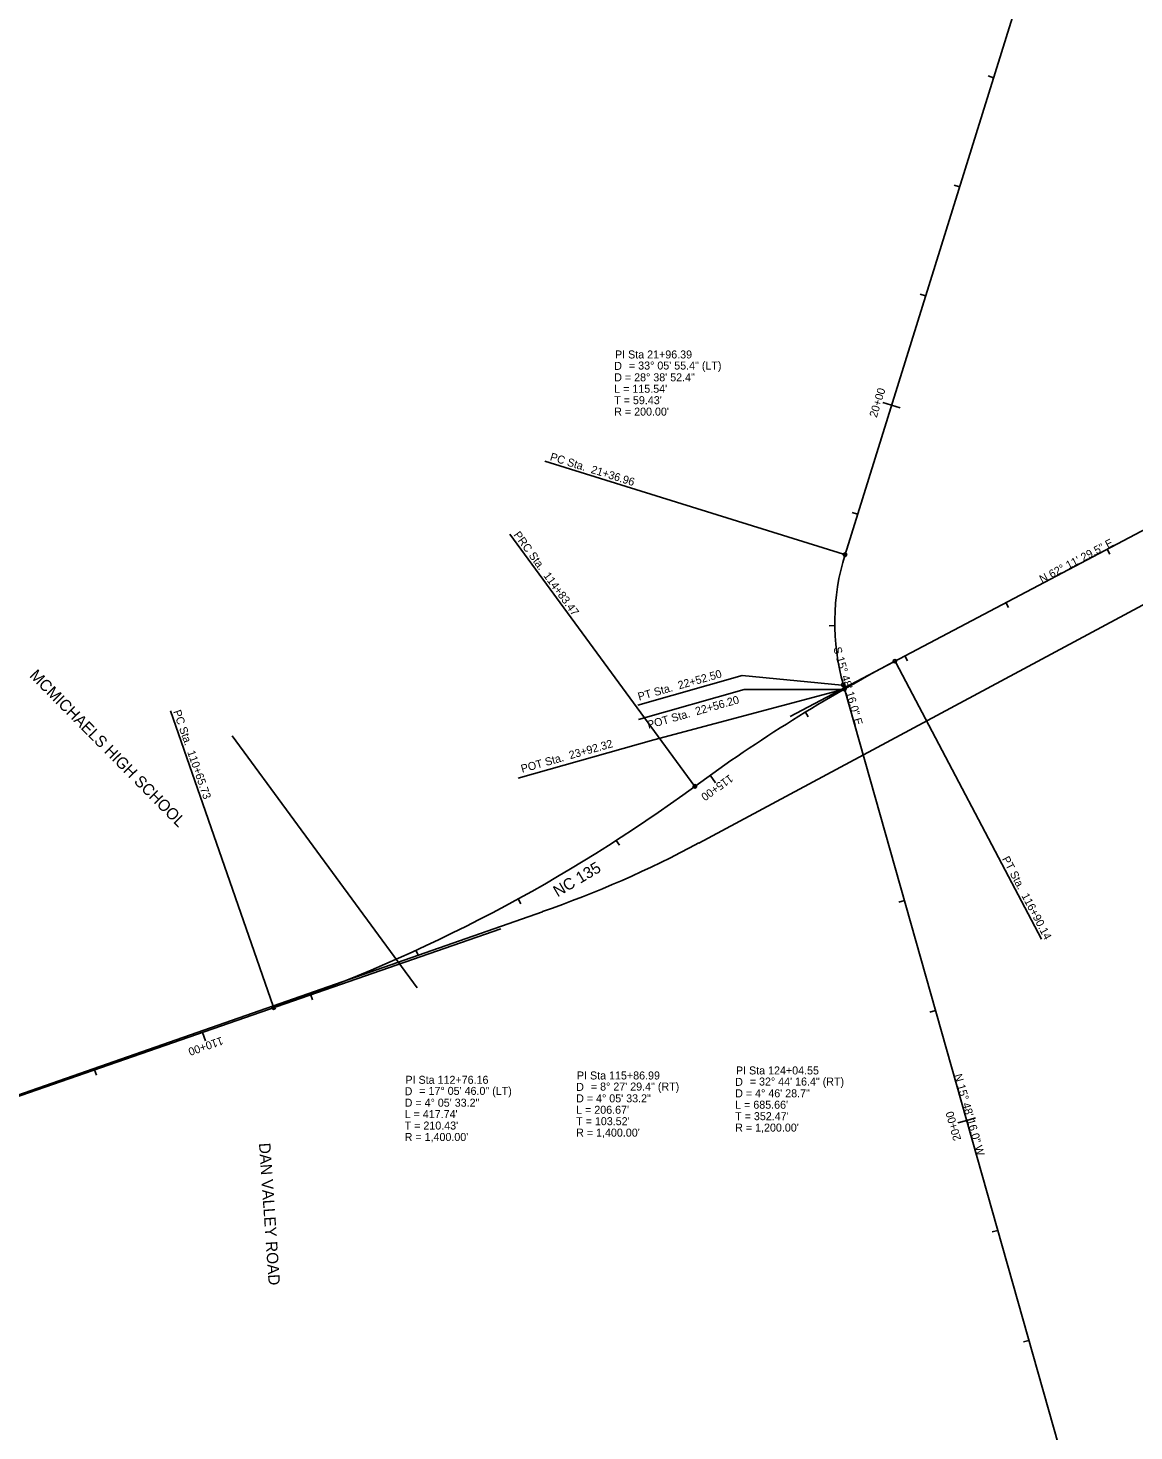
# Model space of a CAD drawing. Extents: x 1722038 to 1726172, y 967033 to 975427.
# Drawn here: x 1722928 to 1723895, y 971142 to 972370 of the extents above; entities that cross this region are included whole.
import ezdxf

# ---------------------------------------------------------------- set-up
doc = ezdxf.new("R2010")
doc.units = 0
for name, color, linetype in [('Prop Horizontal Alignment', 7, 'Continuous'), ('Prop Horizontal Alignment Curve and Spiral Data', 7, 'Continuous'), ('Prop Horizontal Alignment Direction Label', 7, 'Continuous'), ('Prop Horizontal Alignment Station Label', 7, 'Continuous'), ('Prop Horizontal Alignment Tick Label', 7, 'Continuous'), ('Prop Horizontal Alignment Tick Large', 7, 'Continuous'), ('Prop Horizontal Alignment Tick Small', 7, 'Continuous')]:
    doc.layers.add(name, color=color, linetype=linetype)

msp = doc.modelspace()

# ---------------------------------------------------------------- linework, layer by layer
at = {"layer": 'Prop Horizontal Alignment'}
for p, q in [((1723980.3, 972994.6), (1723642.3, 971909)), ((1723594.4, 971767.5), (1724317.8, 972149.1)), ((1723514.4, 971656.7), (1724119.9, 971981.6)), ((1723640.8, 971795.1), (1723641.8, 971791.5)), ((1723852.2, 971048.3), (1723641.8, 971791.5)), ((1722248.4, 971202.3), (1723377.7, 971596.6)), ((1722135.8, 971162.8), (1723341.2, 971581.8))]:
    msp.add_line(p, q, dxfattribs=at)
for centre, radius, start, end in [((1723833.3, 971849.6), 200, 162.7057, 195.8045), ((1724339.1, 970577.5), 1400, 117.8085, 126.2666), ((1722682.7, 972835.1), 1400, 289.1705, 306.2666), ((1723062.9, 972498.2), 954.9, 289.2497, 298.2178)]:
    msp.add_arc(centre, radius, start, end, dxfattribs=at)
at = {"layer": 'Prop Horizontal Alignment Station Label'}
for p, q in [((1723640.9, 971909.5), (1723379.7, 971990.8)), ((1723510.9, 971706.3), (1723349.1, 971926.8)), ((1723686.6, 971814.5), (1723814.2, 971572.6)), ((1723552.3, 971803.2), (1723461, 971777.4)), ((1723639.4, 971794.7), (1723552.3, 971803.2)), ((1723554.1, 971791), (1723461.7, 971764.8)), ((1723640.4, 971791.1), (1723475.2, 971747.1)), ((1723640.4, 971791.1), (1723554.1, 971791)), ((1723142, 971514.1), (1723052.2, 971772.5)), ((1723268.1, 971530), (1723106.3, 971750.6)), ((1723475.2, 971747.1), (1723356.5, 971713.5))]:
    msp.add_line(p, q, dxfattribs=at)
for centre in [(1723642.3, 971909), (1723685.9, 971815.8), (1723640.8, 971795.1), (1723641.8, 971791.5), (1723641.8, 971791.5), (1723510.9, 971706.3), (1723142.5, 971512.7)]:
    msp.add_circle(centre, 1.5, dxfattribs=at)
at = {"layer": 'Prop Horizontal Alignment Tick Large'}
for p, q in [((1723683, 972039.8), (1723675.4, 972042.2)), ((1723683, 972039.8), (1723690.6, 972037.4)), ((1723524.3, 971716), (1723528.9, 971709.5)), ((1723080.4, 971491.1), (1723083, 971483.6)), ((1723748.7, 971414.1), (1723741, 971411.9)), ((1723748.7, 971414.1), (1723756.4, 971416.2))]:
    msp.add_line(p, q, dxfattribs=at)
at = {"layer": 'Prop Horizontal Alignment Tick Small'}
for p, q in [((1723772.2, 972326.2), (1723767.4, 972327.7)), ((1723742.5, 972230.8), (1723737.7, 972232.3)), ((1723712.7, 972135.3), (1723708, 972136.8)), ((1723653.3, 971944.3), (1723648.5, 971945.8)), ((1723871.6, 971913.7), (1723873.9, 971909.3)), ((1723783.1, 971867.1), (1723785.4, 971862.7)), ((1723633.3, 971846.9), (1723628.3, 971846.8)), ((1723694.7, 971820.4), (1723697, 971816)), ((1723607.6, 971771.2), (1723610.2, 971767)), ((1723442.2, 971659), (1723444.9, 971654.8)), ((1723356.3, 971607.8), (1723358.7, 971603.4)), ((1723694.2, 971606.5), (1723689.4, 971605.1)), ((1723267, 971562.8), (1723269.1, 971558.3)), ((1723174.7, 971524.4), (1723176.5, 971519.7)), ((1723721.4, 971510.3), (1723716.6, 971508.9)), ((1722985.9, 971458.3), (1722987.6, 971453.6)), ((1723775.9, 971317.8), (1723771.1, 971316.5)), ((1723803.1, 971221.6), (1723798.3, 971220.3))]:
    msp.add_line(p, q, dxfattribs=at)

# ---------------------------------------------------------------- texts
at = {"layer": 'Prop Horizontal Alignment Curve and Spiral Data'}
for s, p in [('PI Sta 21+96.39', (1723441.1, 972080.6)), ('D', (1723440.4, 972070.6)), ('= 33%%d 05\' 55.4" (LT)', (1723453.3, 972070.9)), ('D = 28%%d 38\' 52.4"', (1723440.4, 972060.6)), ("L = 115.54'", (1723440.4, 972050.6)), ("T = 59.43'", (1723440.4, 972040.6)), ("R = 200.00'", (1723440.4, 972030.6)), ('PI Sta 124+04.55', (1723546.9, 971454.3)), ('PI Sta 112+76.16', (1723257.8, 971446.1)), ('PI Sta 115+86.99', (1723407.8, 971449.9)), ('D', (1723546.2, 971444.3)), ('= 32%%d 44\' 16.4" (RT)', (1723559, 971444.6)), ('D', (1723257.1, 971436.1)), ('= 17%%d 05\' 46.0" (LT)', (1723269.9, 971436.4)), ('D', (1723407.1, 971439.9)), ('D = 4%%d 05\' 33.2"', (1723407.1, 971429.9)), ('= 8%%d 27\' 29.4" (RT)', (1723420, 971440.2)), ('D = 4%%d 46\' 28.7"', (1723546.2, 971434.3)), ('D = 4%%d 05\' 33.2"', (1723257.1, 971426.1)), ("L = 206.67'", (1723407.1, 971419.9)), ("L = 685.66'", (1723546.2, 971424.3)), ("T = 210.43'", (1723257.1, 971406.1)), ("L = 417.74'", (1723257.1, 971416.1)), ("T = 103.52'", (1723407.1, 971409.9)), ("T = 352.47'", (1723546.2, 971414.3)), ("R = 1,200.00'", (1723546.2, 971404.3)), ("R = 1,400.00'", (1723257.1, 971396.1)), ("R = 1,400.00'", (1723407.1, 971399.9))]:
    msp.add_text(s, height=7, dxfattribs=at).set_placement(p)
at = {"layer": 'Prop Horizontal Alignment Direction Label'}
for s, rotation, p in [('N 62%%d 11\' 29.5" E', 27.8085, (1723814.6, 971883.9)), ('S 15%%d 48\' 16.0" E', 285.8045, (1723632, 971827.2)), ('N 15%%d 48\' 16.0" W', 285.8045, (1723737.7, 971453.7))]:
    msp.add_text(s, height=7, rotation=rotation, dxfattribs=at).set_placement(p)
at = {"layer": 'Prop Horizontal Alignment Station Label'}
for s, rotation, p in [('PC Sta.  21+36.96', 342.7057, (1723383.7, 971991.7)), ('PRC Sta.  114+83.47', 306.2666, (1723352, 971926.2)), ('PT Sta.  22+52.50', 15.8045, (1723462.2, 971781.2)), ('POT Sta.  22+56.20', 15.8045, (1723470.4, 971756.5)), ('PC Sta.  110+65.73', 289.1705, (1723054.5, 971771.8)), ('POT Sta.  23+92.32', 15.8045, (1723359.9, 971718.1)), ('PT Sta.  116+90.14', 297.8085, (1723779.4, 971642.9))]:
    msp.add_text(s, height=7, rotation=rotation, dxfattribs=at).set_placement(p)
at = {"layer": 'Prop Horizontal Alignment Tick Label'}
for s, height, rotation, p in [('20+00', 7, 72.7057, (1723670, 972028.4)), ('MCMICHAELS HIGH SCHOOL', 10, 314.5994, (1722928.4, 971802.6)), ('115+00', 7, 215.59, (1723541.3, 971717.1)), ('NC 135', 10, 30.7233, (1723390.8, 971609.2)), ('110+00', 7, 199.1705, (1723096.9, 971487.4)), ('20+00', 7, 105.8045, (1723744, 971397.4)), ('DAN VALLEY ROAD', 10, 273.9511, (1723129.6, 971394.1))]:
    msp.add_text(s, height=height, rotation=rotation, dxfattribs=at).set_placement(p)

doc.saveas('drawing.dxf')
